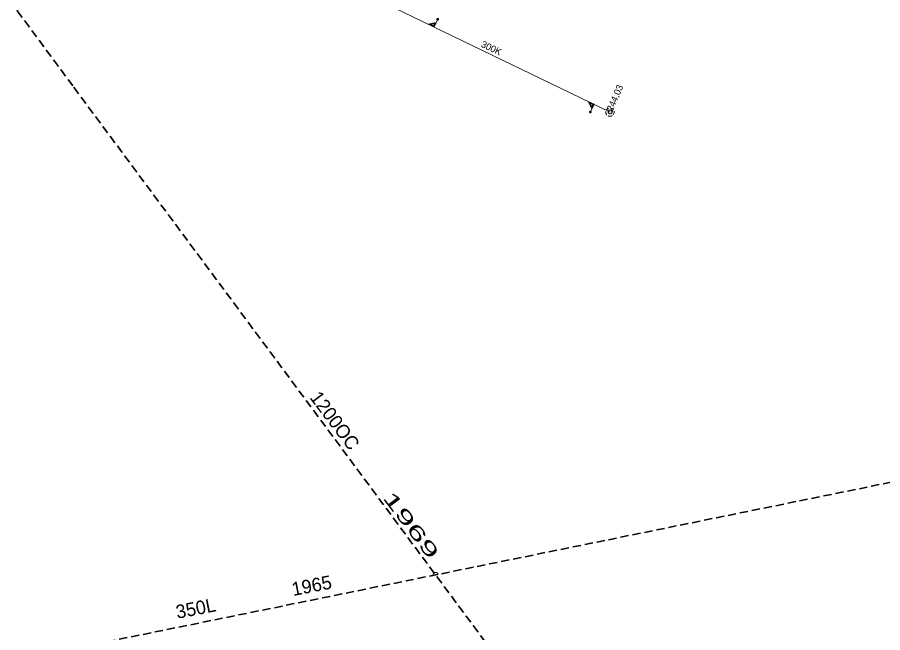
# Model space of a CAD drawing. Extents: x -735085 to -733500, y -1044153 to -1043402.
# Drawn here: x -734694.1 to -734591.8, y -1043715.9 to -1043643.2 of the extents above; entities that cross this region are included whole.
import ezdxf

# ---------------------------------------------------------------- set-up
doc = ezdxf.new("R2010")
doc.units = 0
doc.header["$LTSCALE"] = 0.32
doc.linetypes.add('MEDIUM_DASHED', pattern=[4.5, 3, -1.5])
doc.layers.add('15', color=7, linetype='Continuous')
doc.layers.add('16', color=7, linetype='Continuous')
for name, color, linetype, lineweight in [('18', 7, 'Continuous', 13), ('20', 7, 'Continuous', 13), ('8', 7, 'Continuous', 13)]:
    doc.layers.add(name, color=color, linetype=linetype, lineweight=lineweight)

msp = doc.modelspace()

# ---------------------------------------------------------------- linework, layer by layer
at = {"layer": '18'}
for points in [[(-734644.314, -1043643.316), (-734644.791, -1043644.302), (-734645.484, -1043643.967), (-734644.539, -1043643.781)], [(-734644.636, -1043643.866), (-734644.817, -1043644.241), (-734645.326, -1043643.994), (-734644.635, -1043643.865)], [(-734644.714, -1043643.921), (-734644.841, -1043644.184), (-734645.176, -1043644.022), (-734644.713, -1043643.922)], [(-734626.358, -1043654.432), (-734625.882, -1043653.446), (-734626.576, -1043653.111), (-734626.134, -1043653.967)], [(-734626.128, -1043653.838), (-734625.947, -1043653.463), (-734626.456, -1043653.217), (-734626.129, -1043653.839)], [(-734626.134, -1043653.742), (-734626.007, -1043653.479), (-734626.341, -1043653.318), (-734626.133, -1043653.743)], [(-734624.487, -1043654.289), (-734624.492, -1043654.366), (-734624.487, -1043654.443), (-734624.47, -1043654.518), (-734624.441, -1043654.589), (-734624.401, -1043654.655), (-734624.386, -1043654.677)], [(-734624.142, -1043653.897), (-734624.213, -1043653.925), (-734624.279, -1043653.964), (-734624.34, -1043654.012), (-734624.391, -1043654.069), (-734624.414, -1043654.103)], [(-734623.6, -1043654.08), (-734623.651, -1043654.022), (-734623.708, -1043653.972), (-734623.774, -1043653.931), (-734623.845, -1043653.902), (-734623.894, -1043653.888)], [(-734623.605, -1043654.666), (-734623.565, -1043654.601), (-734623.534, -1043654.531), (-734623.514, -1043654.456), (-734623.507, -1043654.38), (-734623.512, -1043654.303), (-734623.517, -1043654.268)], [(-734624.228, -1043654.806), (-734624.159, -1043654.837), (-734624.083, -1043654.856), (-734624.007, -1043654.863), (-734623.931, -1043654.858), (-734623.855, -1043654.841), (-734623.784, -1043654.813), (-734623.723, -1043654.778)]]:
    msp.add_lwpolyline(points, dxfattribs=at)
for points in [[(-734644.44, -1043643.36), (-734644.449, -1043643.392), (-734644.446, -1043643.426), (-734644.432, -1043643.456), (-734644.407, -1043643.479), (-734644.377, -1043643.492), (-734644.344, -1043643.494), (-734644.311, -1043643.484), (-734644.284, -1043643.464), (-734644.267, -1043643.435), (-734644.261, -1043643.403), (-734644.266, -1043643.369), (-734644.283, -1043643.34), (-734644.308, -1043643.319), (-734644.34, -1043643.307), (-734644.373, -1043643.307), (-734644.404, -1043643.32), (-734644.429, -1043643.343)], [(-734644.416, -1043643.372), (-734644.423, -1043643.4), (-734644.418, -1043643.428), (-734644.401, -1043643.45), (-734644.377, -1043643.465), (-734644.349, -1043643.469), (-734644.323, -1043643.46), (-734644.301, -1043643.441), (-734644.29, -1043643.415), (-734644.29, -1043643.388), (-734644.302, -1043643.362), (-734644.323, -1043643.343), (-734644.35, -1043643.334), (-734644.378, -1043643.338), (-734644.402, -1043643.352)], [(-734626.403, -1043654.306), (-734626.412, -1043654.339), (-734626.409, -1043654.372), (-734626.395, -1043654.402), (-734626.371, -1043654.425), (-734626.34, -1043654.439), (-734626.307, -1043654.441), (-734626.274, -1043654.431), (-734626.248, -1043654.41), (-734626.23, -1043654.382), (-734626.224, -1043654.349), (-734626.229, -1043654.316), (-734626.245, -1043654.287), (-734626.271, -1043654.266), (-734626.302, -1043654.254), (-734626.336, -1043654.254), (-734626.367, -1043654.267), (-734626.393, -1043654.289)], [(-734626.378, -1043654.316), (-734626.385, -1043654.344), (-734626.379, -1043654.372), (-734626.364, -1043654.395), (-734626.339, -1043654.41), (-734626.311, -1043654.413), (-734626.284, -1043654.405), (-734626.263, -1043654.386), (-734626.251, -1043654.36), (-734626.252, -1043654.332), (-734626.263, -1043654.306), (-734626.285, -1043654.287), (-734626.311, -1043654.279), (-734626.339, -1043654.283), (-734626.364, -1043654.297)], [(-734623.757, -1043654.349), (-734623.764, -1043654.297), (-734623.781, -1043654.247), (-734623.809, -1043654.203), (-734623.848, -1043654.166), (-734623.892, -1043654.139), (-734623.943, -1043654.123), (-734623.995, -1043654.118), (-734624.046, -1043654.125), (-734624.095, -1043654.144), (-734624.139, -1043654.174), (-734624.174, -1043654.213), (-734624.201, -1043654.258), (-734624.215, -1043654.309), (-734624.218, -1043654.361), (-734624.21, -1043654.413), (-734624.19, -1043654.461), (-734624.159, -1043654.504), (-734624.12, -1043654.539), (-734624.073, -1043654.563), (-734624.022, -1043654.577), (-734623.97, -1043654.579), (-734623.919, -1043654.569), (-734623.87, -1043654.547), (-734623.828, -1043654.515), (-734623.796, -1043654.475), (-734623.772, -1043654.428), (-734623.759, -1043654.377)]]:
    msp.add_lwpolyline(points, close=True, dxfattribs=at)
at = {"layer": '20'}
msp.add_line((-734623.989, -1043654.36), (-734654.699, -1043639.52), dxfattribs=at)
msp.add_line((-734623.989, -1043654.36), (-734654.699, -1043639.52), dxfattribs=at)
at = {"layer": '8', "linetype": 'MEDIUM_DASHED', "lineweight": 35}
for points in [[(-734668.849, -1043580.305), (-734675.546, -1043596.328), (-734683.508, -1043610.677), (-734694.054, -1043642.408), (-734687.381, -1043651.433), (-734629.763, -1043729.041), (-734628.401, -1043750.135), (-734626.521, -1043774.035)], [(-734687.657, -1043717.791), (-734560.96, -1043692.026), (-734536.445, -1043703.655)]]:
    msp.add_lwpolyline(points, dxfattribs=at)
at = {"layer": '8'}
msp.add_lwpolyline([(-734644.315, -1043708.992), (-734644.323, -1043708.961), (-734644.335, -1043708.932), (-734644.348, -1043708.903), (-734644.365, -1043708.877), (-734644.385, -1043708.852), (-734644.408, -1043708.828), (-734644.432, -1043708.809), (-734644.458, -1043708.79), (-734644.487, -1043708.776), (-734644.517, -1043708.764), (-734644.547, -1043708.756), (-734644.579, -1043708.751), (-734644.61, -1043708.749), (-734644.642, -1043708.75), (-734644.673, -1043708.754), (-734644.704, -1043708.763), (-734644.733, -1043708.774), (-734644.762, -1043708.788), (-734644.789, -1043708.806), (-734644.814, -1043708.825), (-734644.837, -1043708.847), (-734644.857, -1043708.871), (-734644.875, -1043708.899), (-734644.889, -1043708.926), (-734644.901, -1043708.957), (-734644.909, -1043708.987), (-734644.915, -1043709.018), (-734644.917, -1043709.05), (-734644.916, -1043709.081), (-734644.91, -1043709.113)], dxfattribs=at)

# ---------------------------------------------------------------- texts
at = {"layer": '15'}
for s, rotation, p in [('1200OC', 307, (-734659.556, -1043688.098)), ('1965', 11, (-734661.447, -1043711.537)), ('350L', 11, (-734675.14, -1043714.226))]:
    msp.add_text(s, height=1.6, rotation=rotation, dxfattribs=at).set_placement(p)
at = {"layer": '15', "width": 1.95}
msp.add_text('1969', height=1.6, rotation=307, dxfattribs=at).set_placement((-734650.939, -1043699.921))
at = {"layer": '16'}
for s, rotation, p in [('300K', 335, (-734639.313, -1043646.636)), ('244,03', 67, (-734623.69, -1043654.355))]:
    msp.add_text(s, height=0.8, rotation=rotation, dxfattribs=at).set_placement(p)

doc.saveas('drawing.dxf')
